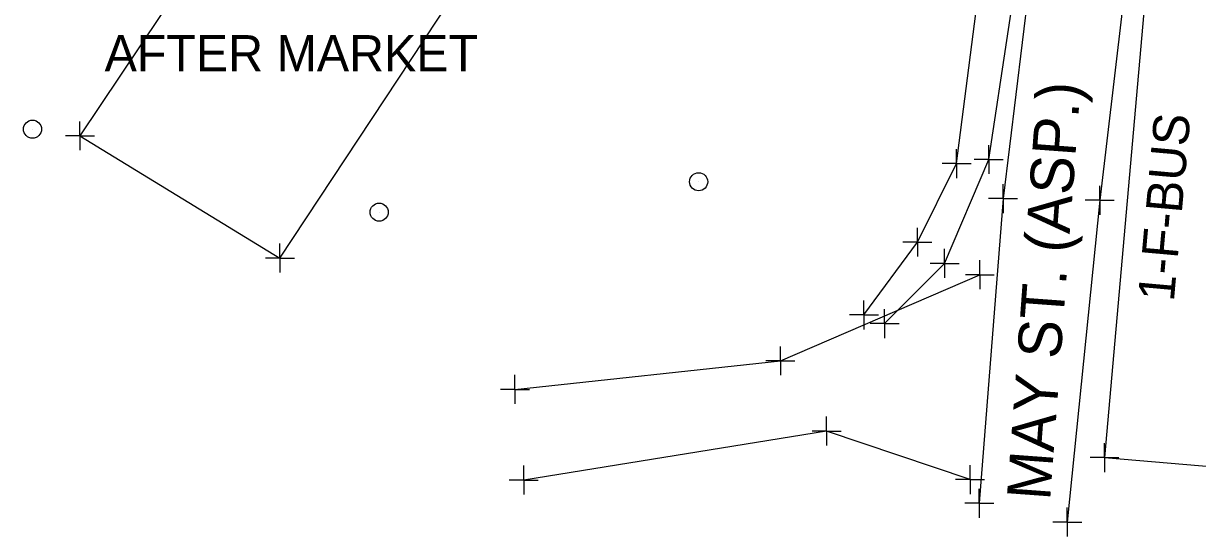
# Model space of a CAD drawing. Extents: x 0 to 1944463, y 0 to 420651.
# Drawn here: x 1942355.2 to 1942517.6, y 417770.3 to 417841.3 of the extents above; entities that cross this region are included whole.
import ezdxf

# ---------------------------------------------------------------- set-up
doc = ezdxf.new("R2010")
doc.units = 0
for name, color, linetype in [('SUR - DTM - Breaklines', 7, 'Continuous'), ('SUR - DTM - Breaklines - Points - Locators', 7, 'Continuous'), ('SUR - DTM - Spot Points - Locators', 7, 'Continuous'), ('SUR - NON-TRAN - Buildings', 7, 'Continuous'), ('SUR - NON-TRAN - Buildings - Points - Locators', 7, 'Continuous'), ('SUR - NON-TRAN - Buildings Text', 7, 'Continuous'), ('SUR - PROPERTY - Property Lines', 7, 'Continuous'), ('SUR - TRAN - Features', 7, 'Continuous'), ('SUR - TRAN - Features - Points - Locators', 7, 'Continuous'), ('SUR - TRAN - Roads', 7, 'Continuous'), ('SUR - TRAN - Roads Text', 7, 'Continuous')]:
    doc.layers.add(name, color=color, linetype=linetype)

msp = doc.modelspace()

# ---------------------------------------------------------------- linework, layer by layer
at = {"layer": 'SUR - DTM - Breaklines'}
for points in [[(1942474.3, 417799.78), (1942482.59, 417808.1), (1942488.69, 417822.47), (1942494.15, 417858.51), (1942495.48, 417877.16), (1942492.16, 417886.7), (1942474.86, 417894.39), (1942438.73, 417907.86)], [(1942471.44, 417800.97), (1942478.82, 417811.04), (1942484.25, 417821.9), (1942489.02, 417859.17), (1942489.02, 417872.99), (1942484.86, 417881.73), (1942475.35, 417886.42), (1942444.92, 417898.63), (1942434.64, 417903.11), (1942430.9, 417892.45), (1942430.42, 417865.8), (1942426.64, 417855.36)]]:
    msp.add_lwpolyline(points, dxfattribs=at)
at = {"layer": 'SUR - DTM - Breaklines - Points - Locators'}
for p, q in [((1942488.69, 417822.47), (1942488.69, 417824.47)), ((1942484.25, 417821.9), (1942484.25, 417823.9)), ((1942484.25, 417821.9), (1942482.25, 417821.9)), ((1942484.25, 417821.9), (1942486.25, 417821.9)), ((1942484.25, 417821.9), (1942484.25, 417819.9)), ((1942488.69, 417822.47), (1942486.69, 417822.47)), ((1942488.69, 417822.47), (1942490.69, 417822.47)), ((1942488.69, 417822.47), (1942488.69, 417820.47)), ((1942478.82, 417811.04), (1942478.82, 417813.04)), ((1942478.82, 417811.04), (1942476.82, 417811.04)), ((1942478.82, 417811.04), (1942480.82, 417811.04)), ((1942478.82, 417811.04), (1942478.82, 417809.04)), ((1942482.59, 417808.1), (1942482.59, 417810.1)), ((1942482.59, 417808.1), (1942480.59, 417808.1)), ((1942482.59, 417808.1), (1942484.59, 417808.1)), ((1942482.59, 417808.1), (1942482.59, 417806.1)), ((1942471.44, 417800.97), (1942471.44, 417802.97)), ((1942474.3, 417799.78), (1942474.3, 417801.78)), ((1942471.44, 417800.97), (1942469.44, 417800.97)), ((1942471.44, 417800.97), (1942473.44, 417800.97)), ((1942471.44, 417800.97), (1942471.44, 417798.97)), ((1942474.3, 417799.78), (1942472.3, 417799.78)), ((1942474.3, 417799.78), (1942476.3, 417799.78)), ((1942474.3, 417799.78), (1942474.3, 417797.78))]:
    msp.add_line(p, q, dxfattribs=at)
at = {"layer": 'SUR - DTM - Spot Points - Locators'}
for p, q in [((1942356.49, 417826.66), (1942356.49, 417826.66)), ((1942448.59, 417819.38), (1942448.59, 417819.38)), ((1942404.42, 417815.18), (1942404.42, 417815.18))]:
    msp.add_line(p, q, dxfattribs=at)
for centre in [(1942356.48, 417826.67), (1942448.58, 417819.39), (1942404.41, 417815.19)]:
    msp.add_circle(centre, 1.25, dxfattribs=at)
at = {"layer": 'SUR - NON-TRAN - Buildings'}
for points in [[(1942363.04, 417825.75), (1942390.69, 417808.84), (1942423.38, 417858.39), (1942396.59, 417875.85)], [(1942539.1, 417850.01), (1942510.98, 417852.33), (1942504.7, 417781.24), (1942533.95, 417778.78), (1942539.15, 417848.98)]]:
    msp.add_lwpolyline(points, close=True, dxfattribs=at)
at = {"layer": 'SUR - NON-TRAN - Buildings - Points - Locators'}
for p, q in [((1942363.04, 417825.75), (1942363.04, 417827.75)), ((1942363.04, 417825.75), (1942361.04, 417825.75)), ((1942363.04, 417825.75), (1942365.04, 417825.75)), ((1942363.04, 417825.75), (1942363.04, 417823.75)), ((1942390.69, 417808.84), (1942390.69, 417810.84)), ((1942390.69, 417808.84), (1942388.69, 417808.84)), ((1942390.69, 417808.84), (1942392.69, 417808.84)), ((1942390.69, 417808.84), (1942390.69, 417806.84)), ((1942504.7, 417781.24), (1942504.7, 417783.24)), ((1942504.7, 417781.24), (1942502.7, 417781.24)), ((1942504.7, 417781.24), (1942506.7, 417781.24)), ((1942504.7, 417781.24), (1942504.7, 417779.24))]:
    msp.add_line(p, q, dxfattribs=at)
at = {"layer": 'SUR - PROPERTY - Property Lines'}
for p, q in [((1942490.67, 417817.07), (1942490.67, 417819.07)), ((1942504.03, 417816.84), (1942504.03, 417818.84)), ((1942490.67, 417817.07), (1942488.67, 417817.07)), ((1942490.67, 417817.07), (1942492.67, 417817.07)), ((1942490.67, 417817.07), (1942490.67, 417815.07)), ((1942504.03, 417816.84), (1942502.03, 417816.84)), ((1942504.03, 417816.84), (1942506.03, 417816.84)), ((1942504.03, 417816.84), (1942504.03, 417814.84)), ((1942487.38, 417774.92), (1942487.38, 417776.92)), ((1942487.38, 417774.92), (1942485.38, 417774.92)), ((1942487.38, 417774.92), (1942489.38, 417774.92)), ((1942487.38, 417774.92), (1942487.38, 417772.92)), ((1942499.55, 417772.32), (1942499.55, 417774.32)), ((1942499.55, 417772.32), (1942497.55, 417772.32)), ((1942499.55, 417772.32), (1942501.55, 417772.32)), ((1942499.55, 417772.32), (1942499.55, 417770.32))]:
    msp.add_line(p, q, dxfattribs=at)
at = {"layer": 'SUR - TRAN - Features'}
for points in [[(1942423.19, 417790.67), (1942459.89, 417794.63), (1942487.46, 417806.53)], [(1942486.11, 417778.19), (1942466.28, 417784.91), (1942424.39, 417778.14)]]:
    msp.add_lwpolyline(points, dxfattribs=at)
at = {"layer": 'SUR - TRAN - Features - Points - Locators'}
for p, q in [((1942487.46, 417806.53), (1942487.46, 417808.53)), ((1942487.46, 417806.53), (1942485.46, 417806.53)), ((1942487.46, 417806.53), (1942489.46, 417806.53)), ((1942487.46, 417806.53), (1942487.46, 417804.53)), ((1942459.89, 417794.63), (1942459.89, 417796.63)), ((1942459.89, 417794.63), (1942457.89, 417794.63)), ((1942459.89, 417794.63), (1942461.89, 417794.63)), ((1942459.89, 417794.63), (1942459.89, 417792.63)), ((1942423.19, 417790.67), (1942423.19, 417792.67)), ((1942423.19, 417790.67), (1942421.19, 417790.67)), ((1942423.19, 417790.67), (1942425.19, 417790.67)), ((1942423.19, 417790.67), (1942423.19, 417788.67)), ((1942466.28, 417784.91), (1942466.28, 417786.91)), ((1942466.28, 417784.91), (1942464.28, 417784.91)), ((1942466.28, 417784.91), (1942468.28, 417784.91)), ((1942466.28, 417784.91), (1942466.28, 417782.91)), ((1942424.39, 417778.14), (1942424.39, 417780.14)), ((1942486.11, 417778.19), (1942486.11, 417780.19)), ((1942424.39, 417778.14), (1942422.39, 417778.14)), ((1942424.39, 417778.14), (1942426.39, 417778.14)), ((1942424.39, 417778.14), (1942424.39, 417776.14)), ((1942486.11, 417778.19), (1942484.11, 417778.19)), ((1942486.11, 417778.19), (1942488.11, 417778.19)), ((1942486.11, 417778.19), (1942486.11, 417776.19))]:
    msp.add_line(p, q, dxfattribs=at)
at = {"layer": 'SUR - TRAN - Roads'}
for points in [[(1942500.23, 417885.72), (1942495.08, 417853.07), (1942490.67, 417817.07), (1942487.38, 417774.92)], [(1942512.19, 417881.21), (1942508.12, 417851.31), (1942504.03, 417816.84), (1942499.55, 417772.32)]]:
    msp.add_lwpolyline(points, dxfattribs=at)

# ---------------------------------------------------------------- texts
at = {"layer": 'SUR - NON-TRAN - Buildings'}
msp.add_text('1-F-BUS', height=5, rotation=84.896, dxfattribs=at).set_placement((1942514.28, 417802.73))
at = {"layer": 'SUR - NON-TRAN - Buildings Text'}
msp.add_text('AFTER MARKET', height=5, dxfattribs=at).set_placement((1942366.45, 417834.68))
at = {"layer": 'SUR - TRAN - Roads Text'}
msp.add_text('MAY ST. (ASP.)', height=6, rotation=85.7988, dxfattribs=at).set_placement((1942497.17, 417775.22))

doc.saveas('drawing.dxf')
